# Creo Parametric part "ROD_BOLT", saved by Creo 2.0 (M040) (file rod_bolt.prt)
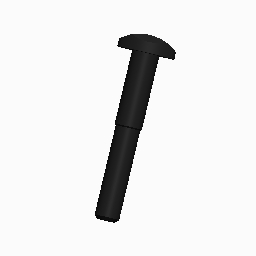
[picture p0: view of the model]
Units: millimeter Kilogram Sec (mmKs); MM, KILOGRAM, SECS

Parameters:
  MATERIAL = "35CrMo"

Created from: INLBS_PART_SOLID.PRT

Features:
  1. datum plane "SIDE", "RIGHT"
  2. datum plane "DTM1", "TOP"
  3. datum plane "DTM2", "FRONT"
  4. coordinate system "ORIGIN"
  5. revolve "Revolve 1", "Section 1"
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
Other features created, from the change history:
  group "COPIED_GROUP"
  extrusion "Extrude 1"
  extruded cut "Extrude 2"
  extruded cut "Extrude 3"
  chamfer "Chamfer 1"
  datum point "CON_WELD"
  round "Round id 160"

Named dimensions: BOLT_D, UP_BOLT_D, UP_LENGTH, LENGTH, CONIC_H, CONIC_V

Surfaces: 9 cylinder, 8 plane, 4 cone, 4 torus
